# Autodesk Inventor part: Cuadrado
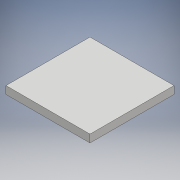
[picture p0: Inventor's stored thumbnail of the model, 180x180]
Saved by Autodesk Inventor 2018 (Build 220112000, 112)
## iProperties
Created: 2020-11
Part Number: Cuadrado
Material: Genérico
Document SubType Name: Modeling
Designer: ULISES
Density: 1 g/cm^3
Appearance: Valor por defecto
Author: ULISES
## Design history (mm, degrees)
sketch "Boceto1"
  geometry: L1 (0, 0)-(35, 0); L2 (35, 0)-(35, 35); L3 (35, 35)-(0, 35); L4 (0, 35)-(0, 0)
  constraints: 8 end point, 2 parallel, 1 horizontal, 1 perpendicular
  dimensions: "d0" = 35 distance of L3.end L1.start; "d1" = 35 distance of L1.start L1.end
extrude "Extrusión1" new body sketch "Boceto1" distance "d2" = 3.2; taper "d3" = 0 deg
node "Sólido1"
